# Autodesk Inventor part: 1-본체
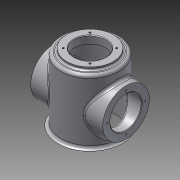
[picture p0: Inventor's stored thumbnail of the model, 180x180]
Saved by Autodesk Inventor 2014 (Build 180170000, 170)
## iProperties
Created: 2015-10
Part Number: 1-본체
Material: 알루미늄 6061
Document SubType Name: Modeling
Designer: Administrator
Density: 2.71 g/cm^3
Appearance: 알루미늄 - 평지
Mass: 986.425 g
Surface Area: 1037.85 cm^2
Volume: 363.995 cm^3
Author: Administrator
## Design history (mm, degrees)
sketch "스케치2"
  geometry: L1 (0, 62.5)-(50, 62.5); L2 (50, 62.5)-(50, -62.5); L3 (50, -62.5)-(0, -62.5); L4 (0, -62.5)-(0, 62.5); L5 (50, 62.5)-(40, 62.5); L6 (40, 62.5)-(40, 57.5); L7 (40, 57.5)-(50, 57.5); L8 (50, 57.5)-(50, 62.5); 2 further points
  constraints: 16 end point, 4 parallel, 2 horizontal, 2 perpendicular, 1 coincident, 1 midpoint
  dimensions: "d2" = 100 diameter of L2 L4; "d3" = 125 distance of L1.end L2.end; "d4" = 80 diameter of L6 L4; "d5" = 120 distance between parallel lines of L3 L7
revolve "회전1" sketch "스케치2" stored, may be unused: angle "d6" = 90 deg
sketch "스케치3"
  geometry: L1 (-60, -60)-(60, -60); L2 (60, -60)-(60, 60); L3 (60, 60)-(-60, 60); L4 (-60, 60)-(-60, -60); 3 further points
  constraints: 8 end point, 2 midpoint, 2 parallel, 2 perpendicular, 1 horizontal, 1 horizontal alignment, 1 vertical alignment
  dimensions: "d7" = 120 distance of L2.end L3.end
extrude "돌출1" join sketch "스케치3" distance "d8" = 10; taper "d9" = 0 deg
fillet "모깎기1" dims "d10" = 10
sketch "스케치4"
  geometry: L1 (50, -62.5)-(-50, -62.5) reference; C1 r 40 at (0, -2.5); 1 further point
  constraints: 1 centre point, 1 midpoint, 1 vertical alignment
  dimensions: "d11" = 80 diameter of C1; "d128" = 60 distance from line of L1 C1.centre
extrude "돌출2" join sketch "스케치4" stored distance "d12" = 124; taper "d13" = 0 deg
hole "구멍1" diameter "d16" = 90; stored, may be unused: countersink angle "d20" = 90 deg, drill point angle "d22" = 0 deg; dims "d14" = 10, "d15" = 10, "d17" = 6, "d18" = 90, "d19" = 112, "d21" = 112
hole "구멍2" diameter "d25" = 54; stored, may be unused: countersink angle "d29" = 90 deg, drill point angle "d31" = 0 deg; dims "d23" = 10, "d24" = 10, "d26" = 6, "d27" = 90, "d28" = 112, "d30" = 13
hole "구멍3" diameter "d34" = 54; stored, may be unused: countersink angle "d38" = 90 deg, drill point angle "d40" = 0 deg; dims "d32" = 10, "d33" = 10, "d35" = 6, "d36" = 90, "d37" = 112, "d39" = 13
sketch "스케치5"
  geometry: L1 (0, 0)-(-22.981, -22.981); L2 (-62, 40)-(-30, 40) reference
  constraints: 2 end point
  dimensions: "d78" = 45 deg angle of L2 L1; "d79" = 32.5 distance of L1.start L1.end
hole "구멍8" sketch "스케치5" at (-22.981, -22.981) diameter "d80" = 3.242; stored, may be unused: countersink angle "d84" = 90 deg, drill point angle "d86" = 118 deg; dims "d81" = 8, "d82" = 90, "d83" = 112, "d85" = 10
sketch "스케치6"
  geometry: L1 (0, 0)-(-32.5, 0); C1 r 27 at (0, 0) reference
  constraints: 2 end point, 1 horizontal
  dimensions: "d144" = 32.5 distance of L1.start L1.end
hole "구멍9" sketch "스케치6" at (-32.5, 0) diameter "d91" = 3.242; stored, may be unused: countersink angle "d95" = 90 deg, drill point angle "d97" = 118 deg; dims "d92" = 8, "d93" = 90, "d94" = 112, "d96" = 10
sketch "스케치7"
  geometry: L1 (0, 0)-(32.5, 0); C1 r 27 at (0, 0) reference
  constraints: 2 end point, 1 horizontal
  dimensions: "d145" = 32.5 distance of L1.start L1.end
hole "구멍10" sketch "스케치7" at (32.5, 0) diameter "d99" = 3.242; stored, may be unused: countersink angle "d103" = 90 deg, drill point angle "d105" = 118 deg; dims "d100" = 8, "d101" = 90, "d102" = 112, "d104" = 10
node "작업 평면1"
sketch "스케치8"
  geometry: L1 (-2.204, 4.065)-(-2.204, 10.935); L2 (-2.204, 10.935)-(2.204, 10.935); L3 (2.204, 10.935)-(2.204, 4.065); L4 (2.204, 4.065)-(-2.204, 4.065); L5 (50, -62.5)-(-50, -62.5) reference; 3 further points
  constraints: 2 midpoint, 1 vertical alignment, 2 other
  dimensions: "d109" = 70 distance from line of L5 point (-2.204, 7.5)
feature "엠보싱1" sketch "스케치8" dims "d2" = 100, "d3" = 125, "d4" = 80, "d5" = 120, "d10" = 10, "d110" = 0.5, "d111" = 0
fillet "모깎기2" dims "d112" = 5
fillet "모깎기3" dims "d113" = 3
fillet "모깎기4" dims "d114" = 3
fillet "모깎기5" dims "d115" = 5
fillet "모깎기6" dims "d116" = 5
chamfer "모따기1" distance "d117" = 3; stored, may be unused: second distance "d118" = 2, angle "d119" = 45 deg
fillet "모깎기7" dims "d120" = 3
fillet "모깎기8" dims "d121" = 3
chamfer "모따기2" distance "d122" = 1; stored, may be unused: second distance "d123" = 2, angle "d124" = 45 deg
chamfer "모따기3" distance "d125" = 1; stored, may be unused: second distance "d126" = 2, angle "d127" = 45 deg
sketch "스케치9"
  geometry: L1 (50, 50)-(-50, 50); L2 (-50, 50)-(-50, -50); L3 (-50, -50)-(50, -50); L4 (50, -50)-(50, 50); 3 further points
  constraints: 8 end point, 2 midpoint, 2 parallel, 1 horizontal, 1 horizontal alignment, 1 perpendicular, 1 vertical alignment
  dimensions: "d129" = 100 distance of L3.end L1.start; "d130" = 100 distance of L2.end L3.end
hole "구멍11" sketch "스케치9" at (50, 50) diameter "d131" = 8; stored, may be unused: countersink angle "d135" = 90 deg, drill point angle "d137" = 118 deg; dims "d132" = 8, "d133" = 90, "d134" = 112, "d136" = 10
node "솔리드1"
pattern_circular "원형 패턴1" dims angle "d88" = 360 deg
pattern_circular "원형 패턴2" dims angle "d107" = 360 deg
pattern_linear "직사각형 패턴1" dims "d140" = 100 (= d129)
